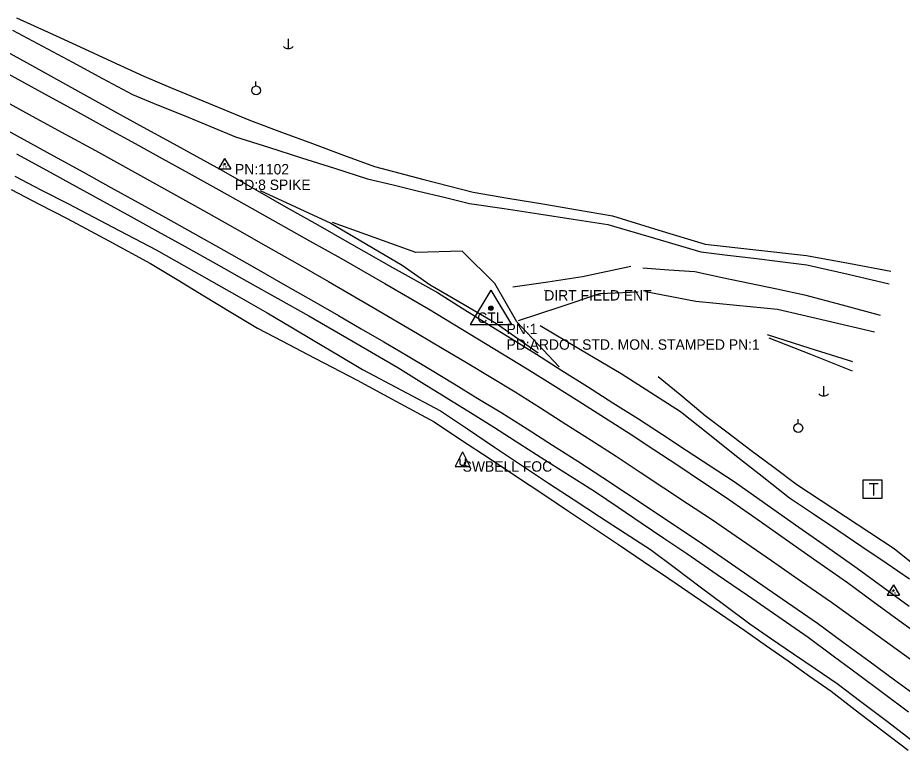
# Model space of a CAD drawing. Extents: x 1193883 to 1197064, y 1474583 to 1477379.
# Drawn here: x 1194308.8 to 1194734.6, y 1476808.7 to 1477161.1 of the extents above; entities that cross this region are included whole.
import ezdxf

# ---------------------------------------------------------------- set-up
doc = ezdxf.new("R2010")
doc.units = 0
for name, color, linetype in [('S_DITCHLINE', 7, 'Continuous'), ('S_DRIVEWAY', 7, 'Continuous'), ('S_EDGE_PAVEMENT', 7, 'Continuous'), ('S_MSC_PT_SYM', 7, 'Continuous'), ('S_PAVEMENT_CROWN', 7, 'Continuous'), ('S_PRIMARY_CTL', 7, 'Continuous'), ('S_PRIMARY_CTL_ANNOT', 7, 'Continuous'), ('S_SECONDARY_CTL', 7, 'Continuous'), ('S_SECONDARY_CTL_ANNOT', 7, 'Continuous'), ('S_SHOULDER', 7, 'Continuous'), ('S_SURVEY_TEXT_ANNOT', 7, 'Continuous'), ('S_TELEPHONE_UTILITIES', 7, 'Continuous'), ('S_UTILITY_POLE', 7, 'Continuous'), ('S_UTILITY_POLE_ANNOT', 7, 'Continuous')]:
    doc.layers.add(name, color=color, linetype=linetype)

msp = doc.modelspace()

# ---------------------------------------------------------------- linework, layer by layer
at = {"layer": 'S_DITCHLINE'}
for points in [[(1194308.2, 1477161.14), (1194323.51, 1477154.1), (1194338.83, 1477147.06), (1194354.14, 1477140.02), (1194369.45, 1477132.98), (1194382.27, 1477127.63), (1194395.1, 1477122.29), (1194407.92, 1477116.95), (1194420.75, 1477111.61), (1194435.71, 1477106.08), (1194450.66, 1477100.55), (1194465.62, 1477095.02), (1194480.58, 1477089.49), (1194504.26, 1477083.36), (1194527.95, 1477077.22), (1194544.71, 1477074.39), (1194561.47, 1477071.55), (1194578.24, 1477068.72), (1194595, 1477065.89), (1194617.33, 1477059.01), (1194639.66, 1477052.13), (1194664.03, 1477049.47), (1194688.4, 1477046.82), (1194708.7, 1477043.05), (1194729, 1477039.29)], [(1194306.32, 1477155.18), (1194320.76, 1477147.45), (1194335.2, 1477139.71), (1194349.64, 1477131.97), (1194364.07, 1477124.24), (1194376.46, 1477119.14), (1194388.86, 1477114.05), (1194401.25, 1477108.96), (1194413.64, 1477103.86), (1194429.53, 1477098.82), (1194445.42, 1477093.78), (1194461.32, 1477088.73), (1194477.21, 1477083.69), (1194489.48, 1477080.72), (1194501.74, 1477077.75), (1194514.01, 1477074.78), (1194526.28, 1477071.82), (1194542.92, 1477069.29), (1194559.55, 1477066.76), (1194576.18, 1477064.23), (1194592.82, 1477061.7), (1194615.22, 1477055.14), (1194637.62, 1477048.58), (1194650.35, 1477046.98), (1194663.09, 1477045.39), (1194675.83, 1477043.8), (1194688.57, 1477042.2), (1194708.43, 1477037.69), (1194728.28, 1477033.17)], [(1194307.32, 1477084.93), (1194320.28, 1477078.25), (1194333.23, 1477071.57), (1194354.28, 1477060.55), (1194375.34, 1477049.53), (1194388.7, 1477041.95), (1194402.06, 1477034.38), (1194415.42, 1477026.8), (1194428.78, 1477019.22), (1194440.27, 1477012.39), (1194451.75, 1477005.56), (1194463.24, 1476998.73), (1194474.72, 1476991.9), (1194493.48, 1476981.96), (1194512.25, 1476972.02), (1194525.27, 1476963.31), (1194538.29, 1476954.59), (1194551.31, 1476945.87), (1194564.33, 1476937.16), (1194576.61, 1476929.19), (1194588.88, 1476921.22), (1194601.15, 1476913.25), (1194613.43, 1476905.28), (1194625.35, 1476896.34), (1194637.28, 1476887.41), (1194649.21, 1476878.47), (1194661.13, 1476869.53), (1194671.64, 1476862.36), (1194682.16, 1476855.18), (1194692.67, 1476848.01), (1194703.18, 1476840.84), (1194714.65, 1476832.2), (1194727.37, 1476822.52), (1194740.1, 1476812.85)], [(1194305.6, 1477078.44), (1194319.09, 1477071.47), (1194332.58, 1477064.51), (1194352.61, 1477053.74), (1194372.64, 1477042.97), (1194385.52, 1477035.16), (1194398.4, 1477027.34), (1194411.28, 1477019.53), (1194424.15, 1477011.72), (1194436.16, 1477005.48), (1194448.17, 1476999.24), (1194460.18, 1476993), (1194472.19, 1476986.76), (1194490.74, 1476976.71), (1194509.29, 1476966.67), (1194522.45, 1476957.95), (1194535.62, 1476949.23), (1194548.78, 1476940.52), (1194561.94, 1476931.8), (1194573.95, 1476923.76), (1194585.96, 1476915.72), (1194597.97, 1476907.67), (1194609.97, 1476899.63), (1194622.18, 1476891.3), (1194634.39, 1476882.98), (1194646.6, 1476874.65), (1194658.82, 1476866.32), (1194669.18, 1476859.03), (1194679.55, 1476851.74), (1194689.92, 1476844.45), (1194700.29, 1476837.16), (1194711.93, 1476828.14), (1194724.64, 1476818.44), (1194737.35, 1476808.74)], [(1194560.24, 1477013.12), (1194579.7, 1477001.58), (1194599.16, 1476990.05), (1194613.46, 1476980.84), (1194627.76, 1476971.64), (1194640.88, 1476961.29), (1194654, 1476950.94), (1194667.12, 1476940.59), (1194680.24, 1476930.24), (1194691.88, 1476922.42), (1194703.52, 1476914.6), (1194715.15, 1476906.77), (1194726.79, 1476898.95), (1194737.95, 1476891.21)], [(1194710.75, 1476995.55), (1194690.22, 1477002.05), (1194669.69, 1477008.54)], [(1194710.61, 1476991.18), (1194690.53, 1476999.12), (1194670.45, 1477007.05)], [(1194617.11, 1476988.61), (1194628.36, 1476979.17), (1194639.6, 1476969.72), (1194650.66, 1476961.45), (1194661.71, 1476953.18), (1194672.77, 1476944.9), (1194683.83, 1476936.63), (1194695.52, 1476928.91), (1194707.2, 1476921.19), (1194718.89, 1476913.46), (1194730.58, 1476905.74), (1194741.15, 1476897.33)]]:
    msp.add_lwpolyline(points, dxfattribs=at)
at = {"layer": 'S_DRIVEWAY'}
for points in [[(1194425.44, 1477078.09), (1194442.46, 1477070.2), (1194459.48, 1477062.3), (1194476.67, 1477052.2), (1194493.87, 1477042.1), (1194507.3, 1477032.71), (1194523.28, 1477023.4), (1194539.27, 1477014.1), (1194559.35, 1476999.96)], [(1194569.41, 1476993.22), (1194559.2, 1477004.04), (1194548.98, 1477014.87), (1194538.36, 1477033.26), (1194522.74, 1477048.8), (1194500.34, 1477048.2), (1194480.32, 1477055.45), (1194460.29, 1477062.7)], [(1194603.91, 1477041.46), (1194580.6, 1477036.48), (1194563.86, 1477033.96), (1194547.13, 1477031.45)], [(1194609.7, 1477040.81), (1194622.18, 1477039.92), (1194634.66, 1477039.02), (1194647.85, 1477036.23), (1194661.04, 1477033.44), (1194674.23, 1477030.64), (1194687.41, 1477027.85), (1194705.68, 1477022.96), (1194723.95, 1477018.06)], [(1194549.85, 1477015.48), (1194569.43, 1477021.96), (1194589.01, 1477028.44), (1194607.42, 1477029.35)], [(1194721.23, 1477009.82), (1194697.84, 1477015.34), (1194674.45, 1477020.85), (1194654.82, 1477022.76), (1194635.18, 1477024.66), (1194610.93, 1477029.29)]]:
    msp.add_lwpolyline(points, dxfattribs=at)
at = {"layer": 'S_EDGE_PAVEMENT'}
for points in [[(1194294.42, 1477139.49), (1194308.91, 1477131.54), (1194323.4, 1477123.59), (1194337.88, 1477115.63), (1194352.37, 1477107.68), (1194365.3, 1477100.56), (1194378.23, 1477093.44), (1194391.15, 1477086.31), (1194404.08, 1477079.19), (1194419.14, 1477070.75), (1194434.2, 1477062.32), (1194449.26, 1477053.88), (1194464.32, 1477045.44), (1194485.41, 1477033.27), (1194506.51, 1477021.1), (1194518.39, 1477013.9), (1194530.28, 1477006.69), (1194542.16, 1476999.49), (1194554.05, 1476992.29), (1194566.41, 1476984.47), (1194578.78, 1476976.66), (1194591.15, 1476968.84), (1194603.51, 1476961.03), (1194614.98, 1476953.43), (1194626.44, 1476945.83), (1194637.91, 1476938.22), (1194649.37, 1476930.62), (1194664.06, 1476920.33), (1194678.75, 1476910.04), (1194693.44, 1476899.76), (1194708.13, 1476889.47), (1194720.6, 1476880.36), (1194733.08, 1476871.25), (1194745.56, 1476862.15)], [(1194297.29, 1477110.37), (1194311.68, 1477102.51), (1194326.07, 1477094.65), (1194340.46, 1477086.79), (1194353.63, 1477079.52), (1194366.8, 1477072.24), (1194379.97, 1477064.96), (1194393.14, 1477057.69), (1194407.94, 1477049.31), (1194422.74, 1477040.92), (1194437.54, 1477032.54), (1194452.34, 1477024.16), (1194463.25, 1477017.83), (1194474.16, 1477011.5), (1194485.07, 1477005.16), (1194495.98, 1476998.83), (1194507.42, 1476991.89), (1194518.87, 1476984.96), (1194530.31, 1476978.02), (1194541.76, 1476971.09), (1194553.94, 1476963.31), (1194566.12, 1476955.53), (1194578.3, 1476947.76), (1194590.47, 1476939.98), (1194601.81, 1476932.45), (1194613.15, 1476924.92), (1194624.49, 1476917.38), (1194635.83, 1476909.85), (1194650.32, 1476899.85), (1194664.81, 1476889.85), (1194679.29, 1476879.85), (1194693.78, 1476869.84), (1194706.11, 1476860.79), (1194718.43, 1476851.75), (1194730.76, 1476842.7), (1194743.09, 1476833.65)]]:
    msp.add_lwpolyline(points, dxfattribs=at)
at = {"layer": 'S_MSC_PT_SYM'}
msp.add_lwpolyline([(1194562.24, 1477030.1), (1194562.24, 1477030.15), (1194562.24, 1477030.1), (1194562.19, 1477030.1), (1194562.24, 1477030.1), (1194562.24, 1477030.05), (1194562.24, 1477030.1), (1194562.29, 1477030.1)], dxfattribs=at)
at = {"layer": 'S_PAVEMENT_CROWN'}
msp.add_lwpolyline([(1194303.2, 1477120.65), (1194317.53, 1477112.84), (1194331.87, 1477105.03), (1194346.21, 1477097.21), (1194359.2, 1477090), (1194372.19, 1477082.79), (1194385.18, 1477075.58), (1194398.17, 1477068.37), (1194413.21, 1477059.86), (1194428.24, 1477051.34), (1194443.28, 1477042.83), (1194458.31, 1477034.31), (1194479.79, 1477021.78), (1194501.28, 1477009.25), (1194513.01, 1477002.22), (1194524.75, 1476995.2), (1194536.48, 1476988.17), (1194548.22, 1476981.15), (1194560.39, 1476973.4), (1194572.55, 1476965.65), (1194584.72, 1476957.91), (1194596.89, 1476950.16), (1194608.34, 1476942.59), (1194619.79, 1476935.03), (1194631.24, 1476927.46), (1194642.69, 1476919.89), (1194657.13, 1476909.93), (1194671.57, 1476899.96), (1194686.01, 1476890), (1194700.45, 1476880.03), (1194713.14, 1476870.86), (1194725.83, 1476861.7), (1194738.53, 1476852.53)], dxfattribs=at)
at = {"layer": 'S_PRIMARY_CTL'}
for p, q in [((1194536.56, 1477030.12), (1194526.52, 1477013.61)), ((1194536.56, 1477030.12), (1194546.38, 1477013.61)), ((1194526.52, 1477013.61), (1194546.38, 1477013.61))]:
    msp.add_line(p, q, dxfattribs=at)
for radius in [1.04, 0.609, 0.344]:
    msp.add_circle((1194536.56, 1477021.42), radius, dxfattribs=at)
at = {"layer": 'S_SECONDARY_CTL'}
for p, q in [((1194408.36, 1477093.37), (1194405.35, 1477088.42)), ((1194408.36, 1477093.37), (1194411.3, 1477088.42)), ((1194405.35, 1477088.42), (1194411.3, 1477088.42)), ((1194730.31, 1476888.26), (1194727.3, 1476883.3)), ((1194730.31, 1476888.26), (1194733.25, 1476883.3)), ((1194727.3, 1476883.3), (1194733.25, 1476883.3))]:
    msp.add_line(p, q, dxfattribs=at)
for centre, radius in [((1194408.36, 1477090.76), 0.311), ((1194408.36, 1477090.76), 0.183), ((1194408.36, 1477090.76), 0.103), ((1194730.31, 1476885.65), 0.311), ((1194730.31, 1476885.65), 0.183), ((1194730.31, 1476885.65), 0.103)]:
    msp.add_circle(centre, radius, dxfattribs=at)
at = {"layer": 'S_SHOULDER'}
for points in [[(1194298.53, 1477147.49), (1194312.98, 1477139.51), (1194327.43, 1477131.53), (1194341.88, 1477123.56), (1194356.33, 1477115.58), (1194369.21, 1477108.51), (1194382.1, 1477101.44), (1194394.98, 1477094.37), (1194407.86, 1477087.29), (1194422.96, 1477078.68), (1194438.07, 1477070.06), (1194453.18, 1477061.44), (1194468.29, 1477052.83), (1194489.55, 1477040.86), (1194510.82, 1477028.89), (1194522.73, 1477021.49), (1194534.64, 1477014.08), (1194546.55, 1477006.68), (1194558.46, 1476999.28), (1194570.73, 1476991.49), (1194583.01, 1476983.71), (1194595.29, 1476975.93), (1194607.56, 1476968.15), (1194619.06, 1476960.64), (1194630.56, 1476953.12), (1194642.06, 1476945.61), (1194653.55, 1476938.1), (1194668.38, 1476927.67), (1194683.2, 1476917.23), (1194698.02, 1476906.8), (1194712.84, 1476896.37), (1194725.34, 1476887.21), (1194737.84, 1476878.06)], [(1194308.13, 1477095.58), (1194322.56, 1477087.76), (1194336.99, 1477079.93), (1194350.1, 1477072.7), (1194363.2, 1477065.48), (1194376.3, 1477058.25), (1194389.4, 1477051.03), (1194404.26, 1477042.71), (1194419.12, 1477034.4), (1194433.98, 1477026.09), (1194448.85, 1477017.78), (1194470.26, 1477005.35), (1194491.68, 1476992.93), (1194503.33, 1476985.68), (1194514.99, 1476978.43), (1194526.64, 1476971.19), (1194538.3, 1476963.94), (1194550.43, 1476956.22), (1194562.57, 1476948.51), (1194574.7, 1476940.8), (1194586.83, 1476933.08), (1194597.83, 1476925.65), (1194608.84, 1476918.22), (1194619.84, 1476910.79), (1194630.84, 1476903.36), (1194645.44, 1476893.32), (1194660.04, 1476883.28), (1194674.64, 1476873.24), (1194689.24, 1476863.2), (1194701.32, 1476854.2), (1194713.4, 1476845.2), (1194725.49, 1476836.2), (1194737.57, 1476827.2)]]:
    msp.add_lwpolyline(points, dxfattribs=at)
at = {"layer": 'S_TELEPHONE_UTILITIES'}
msp.add_lwpolyline([(1194715.74, 1476929.8), (1194715.74, 1476938.8), (1194724.74, 1476938.8), (1194724.74, 1476929.8)], close=True, dxfattribs=at)
at = {"layer": 'S_UTILITY_POLE'}
for p, q in [((1194438.97, 1477151), (1194438.97, 1477146.27)), ((1194423.41, 1477128.3), (1194423.41, 1477130.41)), ((1194696.63, 1476983.96), (1194696.63, 1476979.23)), ((1194684.35, 1476965.93), (1194684.35, 1476968.04)), ((1194522.92, 1476952.3), (1194519.4, 1476945.21)), ((1194522.92, 1476952.3), (1194526.41, 1476945.21)), ((1194521.72, 1476946.45), (1194521.72, 1476948.89)), ((1194522.34, 1476945.79), (1194521.72, 1476946.45)), ((1194524.08, 1476946.45), (1194523.54, 1476945.79)), ((1194524.08, 1476948.89), (1194524.08, 1476946.45)), ((1194519.4, 1476945.21), (1194526.41, 1476945.21)), ((1194523.54, 1476945.79), (1194522.34, 1476945.79))]:
    msp.add_line(p, q, dxfattribs=at)
for centre in [(1194423.53, 1477126.16), (1194684.47, 1476963.79)]:
    msp.add_circle(centre, 2.13, dxfattribs=at)
for centre in [(1194439.03, 1477149.69), (1194696.69, 1476982.65)]:
    msp.add_arc(centre, 3.41, 226.3972, 313.6028, dxfattribs=at)

# ---------------------------------------------------------------- texts
at = {"layer": 'S_PRIMARY_CTL'}
msp.add_text('CTL', height=5, rotation=360, dxfattribs=at).set_placement((1194529.97, 1477014.35))
at = {"layer": 'S_PRIMARY_CTL_ANNOT'}
for s, p in [('PN:1', (1194544.06, 1477008.92)), ('PD:ARDOT STD. MON. STAMPED PN:1', (1194544.06, 1477001.42))]:
    msp.add_text(s, height=5, dxfattribs=at).set_placement(p)
at = {"layer": 'S_SECONDARY_CTL'}
for p in [(1194407.15, 1477088.75), (1194729.1, 1476883.64)]:
    msp.add_text('TV', height=1.5, rotation=360, dxfattribs=at).set_placement(p)
at = {"layer": 'S_SECONDARY_CTL_ANNOT'}
for s, p in [('PN:1102', (1194413.36, 1477085.76)), ('PD:8 SPIKE', (1194413.36, 1477078.26))]:
    msp.add_text(s, height=5, dxfattribs=at).set_placement(p)
at = {"layer": 'S_SURVEY_TEXT_ANNOT'}
msp.add_text('DIRT FIELD ENT', height=5, dxfattribs=at).set_placement((1194562.24, 1477025.1))
at = {"layer": 'S_TELEPHONE_UTILITIES'}
msp.add_text('T', height=6, rotation=360, dxfattribs=at).set_placement((1194718.3, 1476931.3))
at = {"layer": 'S_UTILITY_POLE_ANNOT'}
msp.add_text('SWBELL FOC', height=5, dxfattribs=at).set_placement((1194522.92, 1476942.77))

doc.saveas('drawing.dxf')
